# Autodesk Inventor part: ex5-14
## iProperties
Author: Administrator
Created: 2001-09
Part Number: ex5-14
Document SubType Name: Modeling
Designer: Administrator
Control State: 0
Master: False
Checked Out: False
PropertySet Name: Design Tracking Control
Length Units: 11272
Angle Units: 11279
Time Units: 11290
Mass Units: 11286
Shininess: 3
Angle Display Precision: 2
Document Length Units: 11272
Document Angle Units: 11286
Document Time Units: 11279
Document Mass Units: 11290
Document Length Units Precision: 3
Document Angle Units Precision: 2
Compacted: False
PropertySet Name: _Private Model Information
Density: 0.0
Volumn: 0.0
Area: 0.0
PropertySet Name: Model Information
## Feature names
1. Revolution1
2. Hole1
3. Shell1
4. Loft1
5. Sweep1
6. Mirror1
